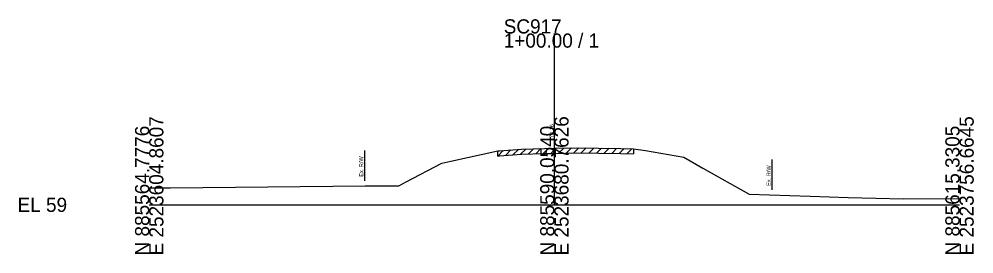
# Model space of a CAD drawing. Extents: x -26 to 218, y -10 to 12021.
# Drawn here: x -25.7 to 162.8, y 990.3 to 1036.7 of the extents above; entities that cross this region are included whole.
import ezdxf

# ---------------------------------------------------------------- set-up
doc = ezdxf.new("R2010")
doc.units = 0
for name, color, linetype in [('RD_GPK_XS_Cell', 7, 'Continuous'), ('RD_XS_ExGround', 7, 'Continuous'), ('RD_XS_ExPaveRet', 7, 'Continuous'), ('RD_XS_ExRW', 7, 'Continuous'), ('RD_XS_TX_Elev_EX', 7, 'Continuous')]:
    doc.layers.add(name, color=color, linetype=linetype)

msp = doc.modelspace()

# ---------------------------------------------------------------- linework, layer by layer
at = {"layer": 'RD_GPK_XS_Cell'}
for p, q in [((80, 1000), (80, 1033.82)), ((0, 1000), (80, 1000)), ((80, 1000), (160, 1000))]:
    msp.add_line(p, q, dxfattribs=at)
at = {"layer": 'RD_XS_ExGround'}
for p, q in [((59.54, 1008.59), (68.82, 1010.63)), ((68.82, 1010.63), (69.18, 1010.66)), ((69.18, 1010.66), (73.52, 1010.99)), ((73.52, 1010.99), (78.08, 1011.11)), ((78.08, 1011.11), (80, 1011.16)), ((80, 1011.16), (84.3, 1011.27)), ((84.3, 1011.27), (93.12, 1011.1)), ((93.12, 1011.1), (95.6, 1011.06)), ((95.6, 1011.06), (98, 1010.69)), ((98, 1010.69), (105.59, 1009.43)), ((105.59, 1009.43), (109.32, 1007.21)), ((50.76, 1004.51), (57.81, 1008.2)), ((57.81, 1008.2), (59.54, 1008.59)), ((109.32, 1007.21), (118.45, 1002.12)), ((0, 1003.38), (4.17, 1003.36)), ((4.17, 1003.36), (42.66, 1003.75)), ((42.66, 1003.75), (47.07, 1003.76)), ((47.07, 1003.76), (49.32, 1003.76)), ((49.32, 1003.76), (50.76, 1004.51)), ((118.45, 1002.12), (130.54, 1001.69)), ((130.54, 1001.69), (138.01, 1001.42)), ((138.01, 1001.42), (148.95, 1001.18)), ((148.95, 1001.18), (160, 1001.25))]:
    msp.add_line(p, q, dxfattribs=at)
at = {"layer": 'RD_XS_ExPaveRet'}
for p, q in [((68.82, 1009.63), (69.9, 1010.71)), ((68.82, 1009.63), (68.82, 1010.63)), ((70.32, 1009.74), (71.4, 1010.83)), ((71.82, 1009.86), (72.9, 1010.94)), ((73.32, 1009.97), (74.36, 1011.01)), ((74.82, 1010.02), (75.85, 1011.05)), ((76.32, 1010.06), (77.35, 1011.09)), ((77.82, 1010.1), (78.85, 1011.13)), ((79.32, 1010.14), (80.35, 1011.17)), ((80.82, 1010.18), (81.85, 1011.21)), ((82.32, 1010.22), (83.35, 1011.25)), ((83.82, 1010.26), (84.82, 1011.26)), ((85.32, 1010.25), (86.3, 1011.23)), ((86.82, 1010.22), (87.8, 1011.21)), ((88.32, 1010.2), (89.3, 1011.18)), ((89.82, 1010.17), (90.8, 1011.15)), ((91.32, 1010.14), (92.3, 1011.12)), ((92.82, 1010.11), (93.8, 1011.09)), ((94.32, 1010.08), (95.3, 1011.06)), ((95.6, 1011.06), (95.6, 1010.06)), ((68.82, 1009.63), (69.18, 1009.66)), ((69.18, 1009.66), (73.52, 1009.99)), ((73.52, 1009.99), (78.08, 1010.11)), ((78.08, 1010.11), (80, 1010.16)), ((80, 1010.16), (84.3, 1010.27)), ((84.3, 1010.27), (93.12, 1010.1)), ((93.12, 1010.1), (95.6, 1010.06))]:
    msp.add_line(p, q, dxfattribs=at)
at = {"layer": 'RD_XS_ExRW'}
for p, q in [((42.5, 1010.75), (42.5, 1004.75)), ((122.97, 1008.96), (122.97, 1002.96))]:
    msp.add_line(p, q, dxfattribs=at)

# ---------------------------------------------------------------- texts
at = {"layer": 'RD_GPK_XS_Cell'}
for s, p in [('SC917', (70, 1033.82)), ('1+00.00 / 1', (70, 1031.02)), ('EL 59', (-26, 998.6))]:
    msp.add_text(s, height=2.8, dxfattribs=at).set_placement(p)
for s, p in [('E 2523604.8607', (2.8, 990)), ('E 2523680.7626', (82.8, 990)), ('E 2523756.6645', (162.8, 990)), ('N 885564.7776', (0, 990)), ('N 885590.0540', (80, 990)), ('N 885615.3305', (160, 990))]:
    msp.add_text(s, height=2.8, rotation=90, dxfattribs=at).set_placement(p)
at = {"layer": 'RD_XS_ExRW'}
for p in [(42.25, 1005.53), (122.72, 1003.74)]:
    msp.add_text('Ex. R/W ', height=0.8, rotation=90, dxfattribs=at).set_placement(p)
at = {"layer": 'RD_XS_TX_Elev_EX'}
msp.add_text('70.16', height=0.8, rotation=90, dxfattribs=at).set_placement((79.9, 1013.16))

doc.saveas('drawing.dxf')
